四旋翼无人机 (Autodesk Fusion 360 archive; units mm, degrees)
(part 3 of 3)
sketch "草图4" plane through (0, 1.5, 0) normal (0, 1, 0) x axis (-1, 0, 0)
  line L1 (-17, -12) -> (-2, -12)
  line L2 (-18, -13) -> (-17, -12)
  line L3 (-18, -15) -> (-18, -13)
  line L4 (15, -18) -> (-15, -18)
  line L5 (18, -13) -> (18, -15)
  line L6 (17, -12) -> (18, -13)
  line L7 (17, 12) -> (17, -12)
  line L8 (18, 13) -> (17, 12)
  line L9 (18, 15) -> (18, 13)
  line L10 (-15, 18) -> (15, 18)
  line L11 (-18, 13) -> (-18, 15)
  line L12 (-17, 12) -> (-18, 13)
  line L13 (-17, -8.9856) -> (-17, 12)
  line L14 (-16.0181, -7.3474) -> (-17, -8.9856)
  line L15 (-16.0181, 3) -> (-16.0181, -7.3474)
  line L16 (-2, 3) -> (-16.0181, 3)
  line L17 (-2, -12) -> (-2, 3)
  line L18 (-5, 13.5) -> (5, 13.5)
  line L19 (-5, 18) -> (-5, 13.5)
  line L20 (5, 18) -> (-5, 18)
  line L21 (5, 13.5) -> (5, 18)
  arc A1 centre (-15, -15) radius 3 clockwise from (-15, -18) to (-18, -15)
  arc A2 centre (15, -15) radius 3 clockwise from (18, -15) to (15, -18)
  arc A3 centre (15, 15) radius 3 clockwise from (15, 18) to (18, 15)
  arc A4 centre (-15, 15) radius 3 clockwise from (-18, 15) to (-15, 18)
  circle C1 centre (-15, 15) radius 2
  circle C2 centre (15, 15) radius 2
  circle C3 centre (15, -15) radius 2
  circle C4 centre (-15, -15) radius 2
  point P33 (-5, 18)
  point P35 (0, 13.5)
  point P1 (0, 0)
  point P31 (5, 13.5)
  point P32 (-5, 13.5)
  horizontal L18
  vertical L19
  horizontal L20
  vertical L21
  coincident L10 P33
  midpoint L18 P35
  vertical P1 P35
  dimension "d23" distance P31 P32 = 10
  dimension "d24" distance P32 P33 = 4.5
extrude "拉伸4" add sketch "草图4" profile of L10 L18 L19 L20 L21 along normal blind 3
sketch "草图5" plane through (0, 1.5, 0) normal (0, 1, 0) x axis (-1, 0, 0)
  line L1 (-5, 18) -> (-5, 13.5)
  line L2 (-15, 18) -> (-5, 18)
  line L3 (-18, 13) -> (-18, 15)
  line L4 (-17, 12) -> (-18, 13)
  line L5 (-17, -8.9856) -> (-17, 12)
  line L6 (-16.0181, -7.3474) -> (-17, -8.9856)
  line L7 (-16.0181, 3) -> (-16.0181, -7.3474)
  line L8 (-2, 3) -> (-16.0181, 3)
  line L9 (-2, -12) -> (-2, 3)
  line L10 (-17, -12) -> (-2, -12)
  line L11 (-18, -13) -> (-17, -12)
  line L12 (-18, -15) -> (-18, -13)
  line L13 (15, -18) -> (-15, -18)
  line L14 (18, -13) -> (18, -15)
  line L15 (17, -12) -> (18, -13)
  line L16 (17, 12) -> (17, -12)
  line L17 (18, 13) -> (17, 12)
  line L18 (18, 15) -> (18, 13)
  line L19 (5, 18) -> (15, 18)
  line L20 (5, 13.5) -> (5, 18)
  line L21 (-5, 13.5) -> (5, 13.5)
  line L22 (6.5346, -12) -> (11, -12)
  line L23 (6.5346, -2.267) -> (6.5346, -12)
  line L24 (11, -2.267) -> (6.5346, -2.267)
  line L25 (11, -12) -> (11, -2.267)
  line L26 (6.2413, 4.9227) -> (11.8936, 4.9227)
  line L27 (6.2413, 10.575) -> (6.2413, 4.9227)
  line L28 (11.8936, 10.575) -> (6.2413, 10.575)
  line L29 (11.8936, 4.9227) -> (11.8936, 10.575)
  line L30 (4.0838, 6.9737) -> (5.1098, 6.9737)
  line L31 (4.0838, 8.524) -> (4.0838, 6.9737)
  line L32 (5.1098, 8.524) -> (4.0838, 8.524)
  line L33 (5.1098, 6.9737) -> (5.1098, 8.524)
  line L34 (0.5, 6.4497) -> (3.0982, 6.4497)
  line L35 (0.5, 9.048) -> (0.5, 6.4497)
  line L36 (3.0982, 9.048) -> (0.5, 9.048)
  line L37 (3.0982, 6.4497) -> (3.0982, 9.048)
  line L38 (-6.7587, 4.9227) -> (-1.1064, 4.9227)
  line L39 (-9.9018, 6.4497) -> (-9.9018, 9.048)
  line L40 (-8.9162, 6.9737) -> (-7.8902, 6.9737)
  line L41 (-1.1064, 4.9227) -> (-1.1064, 10.575)
  line L42 (-12.5, 6.4497) -> (-9.9018, 6.4497)
  line L43 (-6.7587, 10.575) -> (-6.7587, 4.9227)
  line L44 (-12.5, 9.048) -> (-12.5, 6.4497)
  line L45 (-7.8902, 8.524) -> (-8.9162, 8.524)
  line L46 (-9.9018, 9.048) -> (-12.5, 9.048)
  line L47 (-8.9162, 8.524) -> (-8.9162, 6.9737)
  line L48 (-1.1064, 10.575) -> (-6.7587, 10.575)
  line L49 (-7.8902, 6.9737) -> (-7.8902, 8.524)
  arc A1 centre (-15, 15) radius 3 clockwise from (-18, 15) to (-15, 18)
  arc A2 centre (-15, -15) radius 3 clockwise from (-15, -18) to (-18, -15)
  arc A3 centre (15, -15) radius 3 clockwise from (18, -15) to (15, -18)
  arc A4 centre (15, 15) radius 3 clockwise from (15, 18) to (18, 15)
  circle C1 centre (15, -15) radius 2
  circle C2 centre (15, 15) radius 2
  circle C3 centre (-15, 15) radius 2
  circle C4 centre (-15, -15) radius 2
  point P51 (3.0982, 7.7488)
  point P52 (4.0838, 7.7488)
  point P53 (6.2413, 7.7488)
  horizontal L22
  vertical L23
  horizontal L24
  vertical L25
  horizontal L26
  vertical L27
  horizontal L28
  vertical L29
  horizontal L30
  vertical L31
  horizontal L32
  vertical L33
  horizontal L34
  vertical L35
  horizontal L36
  vertical L37
  equal L26 L27
  equal L34 L37
  midpoint L37 P51
  midpoint L31 P52
  horizontal P51 P52
  midpoint L27 P53
  horizontal P52 P53
  dimension "d29" R-Pattern1-uDistance = -13
  dimension "d30" R-Pattern1-vDistance = 0
extrude "拉伸5" add sketch "草图5" profile of L22 L23 L24 L25 L26 L27 L28 L29 L30 L31 L32 L33 L34 L35 L36 L37 L38 L39 L40 L41 L42 L43 L44 L45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 along normal blind 1
sketch "草图6" plane through (0, 1.5, 0) normal (0, 1, 0) x axis (-1, 0, 0)
  line L1 (11, -12) -> (11, -2.267)
  line L2 (6.5346, -12) -> (11, -12)
  line L3 (6.5346, -2.267) -> (6.5346, -12)
  line L4 (11, -2.267) -> (6.5346, -2.267)
  line L5 (3.0982, 6.4497) -> (3.0982, 9.048)
  line L6 (0.5, 6.4497) -> (3.0982, 6.4497)
  line L7 (0.5, 9.048) -> (0.5, 6.4497)
  line L8 (3.0982, 9.048) -> (0.5, 9.048)
  line L9 (5.1098, 6.9737) -> (5.1098, 8.524)
  line L10 (4.0838, 6.9737) -> (5.1098, 6.9737)
  line L11 (4.0838, 8.524) -> (4.0838, 6.9737)
  line L12 (5.1098, 8.524) -> (4.0838, 8.524)
  line L13 (-9.9018, 9.048) -> (-12.5, 9.048)
  line L14 (-9.9018, 6.4497) -> (-9.9018, 9.048)
  line L15 (-12.5, 6.4497) -> (-9.9018, 6.4497)
  line L16 (-12.5, 9.048) -> (-12.5, 6.4497)
  line L17 (-1.1064, 10.575) -> (-6.7587, 10.575)
  line L18 (-1.1064, 4.9227) -> (-1.1064, 10.575)
  line L19 (-6.7587, 4.9227) -> (-1.1064, 4.9227)
  line L20 (-6.7587, 10.575) -> (-6.7587, 4.9227)
  line L21 (11.8936, 4.9227) -> (11.8936, 10.575)
  line L22 (6.2413, 4.9227) -> (11.8936, 4.9227)
  line L23 (6.2413, 10.575) -> (6.2413, 4.9227)
  line L24 (11.8936, 10.575) -> (6.2413, 10.575)
  line L25 (-7.8902, 6.9737) -> (-7.8902, 8.524)
  line L26 (-8.9162, 6.9737) -> (-7.8902, 6.9737)
  line L27 (-8.9162, 8.524) -> (-8.9162, 6.9737)
  line L28 (-7.8902, 8.524) -> (-8.9162, 8.524)
  line L29 (-5, 18) -> (-5, 13.5)
  line L30 (-15, 18) -> (-5, 18)
  line L31 (-18, 13) -> (-18, 15)
  line L32 (-17, 12) -> (-18, 13)
  line L33 (-17, -8.9856) -> (-17, 12)
  line L34 (-16.0181, -7.3474) -> (-17, -8.9856)
  line L35 (-16.0181, 3) -> (-16.0181, -7.3474)
  line L36 (-2, 3) -> (-16.0181, 3)
  line L37 (-2, -12) -> (-2, 3)
  line L38 (-17, -12) -> (-2, -12)
  line L39 (-18, -13) -> (-17, -12)
  line L40 (-18, -15) -> (-18, -13)
  line L41 (15, -18) -> (-15, -18)
  line L42 (18, -13) -> (18, -15)
  line L43 (17, -12) -> (18, -13)
  line L44 (17, 12) -> (17, -12)
  line L45 (18, 13) -> (17, 12)
  line L46 (18, 15) -> (18, 13)
  line L47 (5, 18) -> (15, 18)
  line L48 (5, 13.5) -> (5, 18)
  line L49 (-5, 13.5) -> (5, 13.5)
  line L50 (9.3337, -1) -> (12, -1)
  line L51 (9.3337, 0.4013) -> (9.3337, -1)
  line L52 (12, 0.4013) -> (9.3337, 0.4013)
  line L53 (12, -1) -> (12, 0.4013)
  line L54 (9.3337, 1.5747) -> (12, 1.5747)
  line L55 (9.3337, 2.8319) -> (9.3337, 1.5747)
  line L56 (12, 2.8319) -> (9.3337, 2.8319)
  line L57 (12, 1.5747) -> (12, 2.8319)
  line L58 (5.8554, -0.7302) -> (7.4478, -0.7302)
  line L59 (5.8554, 2.2033) -> (5.8554, -0.7302)
  line L60 (7.4478, 2.2033) -> (5.8554, 2.2033)
  line L61 (7.4478, -0.7302) -> (7.4478, 2.2033)
  line L62 (1.6646, -11.4165) -> (3.0476, -11.4165)
  line L63 (1.6646, -10.6622) -> (1.6646, -11.4165)
  line L64 (3.0476, -10.6622) -> (1.6646, -10.6622)
  line L65 (3.0476, -11.4165) -> (3.0476, -10.6622)
  line L66 (1, -9.2374) -> (3.5505, -9.2374)
  line L67 (1, -8) -> (1, -9.2374)
  line L68 (3.5505, -8) -> (1, -8)
  line L69 (3.5505, -9.2374) -> (3.5505, -8)
  line L70 (1.6646, -7) -> (3, -7)
  line L71 (1.6646, -6.0524) -> (1.6646, -7)
  line L72 (3, -6.0524) -> (1.6646, -6.0524)
  line L73 (3, -7) -> (3, -6.0524)
  line L74 (1.6646, -1.4426) -> (3.9695, -1.4426)
  line L75 (1.6646, -0.3949) -> (1.6646, -1.4426)
  line L76 (3.9695, -0.3949) -> (1.6646, -0.3949)
  line L77 (3.9695, -1.4426) -> (3.9695, -0.3949)
  arc A1 centre (-15, 15) radius 3 clockwise from (-18, 15) to (-15, 18)
  arc A2 centre (-15, -15) radius 3 clockwise from (-15, -18) to (-18, -15)
  arc A3 centre (15, -15) radius 3 clockwise from (18, -15) to (15, -18)
  arc A4 centre (15, 15) radius 3 clockwise from (15, 18) to (18, 15)
  circle C1 centre (15, -15) radius 2
  circle C2 centre (15, 15) radius 2
  circle C3 centre (-15, 15) radius 2
  circle C4 centre (-15, -15) radius 2
  horizontal L50
  vertical L51
  horizontal L52
  vertical L53
  horizontal L54
  vertical L55
  horizontal L56
  vertical L57
  horizontal L58
  vertical L59
  horizontal L60
  vertical L61
  horizontal L62
  vertical L63
  horizontal L64
  vertical L65
  horizontal L66
  vertical L67
  horizontal L68
  vertical L69
  horizontal L70
  vertical L71
  horizontal L72
  vertical L73
  horizontal L74
  vertical L75
  horizontal L76
  vertical L77
extrude "拉伸6" add sketch "草图6" profile of L50 L51 L52 L53 L54 L55 L56 L57 L58 L59 L60 L61 L62 L63 L64 L65 L66 L67 L68 L69 L70 L71 L72 L73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 along normal blind 0.5
sketch "草图7" plane through (0, 0, 0) normal (0, -1, 0) x axis (1, 0, 0)
  line L1 (-17, 12) -> (-18, 13)
  line L2 (-17, -12) -> (-17, 12)
  line L3 (-18, -13) -> (-17, -12)
  line L4 (-18, -15) -> (-18, -13)
  line L5 (15, -18) -> (-15, -18)
  line L6 (18, -13) -> (18, -15)
  line L7 (17, -12) -> (18, -13)
  line L8 (17, 12) -> (17, -12)
  line L9 (18, 13) -> (17, 12)
  line L10 (18, 15) -> (18, 13)
  line L11 (-15, 18) -> (15, 18)
  line L12 (-18, 13) -> (-18, 15)
  line L13 (-4.5, -6) -> (5, -6)
  line L14 (-4.5, 3.5) -> (-4.5, -6)
  line L15 (5, 3.5) -> (-4.5, 3.5)
  line L16 (5, -6) -> (5, 3.5)
  circle C1 centre (-15, -15) radius 2
  circle C2 centre (-15, 15) radius 2
  circle C3 centre (15, 15) radius 2
  circle C4 centre (15, -15) radius 2
  arc A1 centre (-15, -15) radius 3 clockwise from (-15, -18) to (-18, -15)
  arc A2 centre (15, -15) radius 3 clockwise from (18, -15) to (15, -18)
  arc A3 centre (15, 15) radius 3 clockwise from (15, 18) to (18, 15)
  arc A4 centre (-15, 15) radius 3 clockwise from (-18, 15) to (-15, 18)
  point P27 (-4.5, -6)
  point P28 (-4.5, 3.5)
  horizontal L13
  vertical L14
  horizontal L15
  vertical L16
  equal L13 L16
  dimension "d35" distance P27 P28 = 9.5
  dimension "d36" distance L8 L16 = 12
  dimension "d40" distance L5 L13 = 12
circular_pattern "C-阵列" TotalAngle -90
chamfer "倒角2" distance 1
extrude "拉伸7" add sketch "草图7" profile of L13 L14 L15 L16 along normal blind 1
sketch "草图8" plane through (0, 0, 0) normal (0, -1, 0) x axis (1, 0, 0)
  line L1 (5, -6) -> (5, 3.5)
  line L2 (-4.5, -6) -> (5, -6)
  line L3 (-4.5, 3.5) -> (-4.5, -6)
  line L4 (5, 3.5) -> (-4.5, 3.5)
  line L5 (13, -18) -> (12, -17)
  line L6 (15, -18) -> (13, -18)
  line L7 (18, -13) -> (18, -15)
  line L8 (17, -12) -> (18, -13)
  line L9 (17, 12) -> (17, -12)
  line L10 (18, 13) -> (17, 12)
  line L11 (18, 15) -> (18, 13)
  line L12 (-15, 18) -> (15, 18)
  line L13 (-18, 13) -> (-18, 15)
  line L14 (-17, 12) -> (-18, 13)
  line L15 (-17, -12) -> (-17, 12)
  line L16 (-18, -13) -> (-17, -12)
  line L17 (-18, -15) -> (-18, -13)
  line L18 (-13, -18) -> (-15, -18)
  line L19 (-12, -17) -> (-13, -18)
  line L20 (12, -17) -> (-12, -17)
  line L21 (-12, -3.5) -> (-18, -3.5)
  line L22 (-12, -11) -> (-12, -3.5)
  line L23 (-18, -11) -> (-12, -11)
  line L24 (-18, -3.5) -> (-18, -11)
  arc A1 centre (15, -15) radius 3 clockwise from (18, -15) to (15, -18)
  arc A2 centre (15, 15) radius 3 clockwise from (15, 18) to (18, 15)
  arc A3 centre (-15, 15) radius 3 clockwise from (-18, 15) to (-15, 18)
  arc A4 centre (-15, -15) radius 3 clockwise from (-15, -18) to (-18, -15)
  circle C1 centre (15, -15) radius 2
  circle C2 centre (15, 15) radius 2
  circle C3 centre (-15, 15) radius 2
  circle C4 centre (-15, -15) radius 2
  point P24 (-18, -13)
  point P37 (-18, -11)
  point P34 (-18, -3.5)
  point P35 (-12, -3.5)
  horizontal L21
  vertical L22
  horizontal L23
  vertical L24
  vertical P24 P37
  dimension "d43" distance P34 P37 = 7.5
  dimension "d44" distance P34 P35 = 6
  dimension "d45" distance L18 L23 = 7
extrude "拉伸8" add sketch "草图8" profile of L15 L21 L22 L23 L24 along normal blind 3
sketch "草图9" plane through (0, 0, 0) normal (0, -1, 0) x axis (1, 0, 0)
  line L1 (-17, -11) -> (-12, -11)
  line L2 (-17, -12) -> (-17, -11)
  line L3 (-18, -13) -> (-17, -12)
  line L4 (-18, -15) -> (-18, -13)
  line L5 (-13, -18) -> (-15, -18)
  line L6 (-12, -17) -> (-13, -18)
  line L7 (12, -17) -> (-12, -17)
  line L8 (13, -18) -> (12, -17)
  line L9 (15, -18) -> (13, -18)
  line L10 (18, -13) -> (18, -15)
  line L11 (17, -12) -> (18, -13)
  line L12 (17, 12) -> (17, -12)
  line L13 (18, 13) -> (17, 12)
  line L14 (18, 15) -> (18, 13)
  line L15 (-15, 18) -> (15, 18)
  line L16 (-18, 13) -> (-18, 15)
  line L17 (-17, 12) -> (-18, 13)
  line L18 (-17, -3.5) -> (-17, 12)
  line L19 (-12, -3.5) -> (-17, -3.5)
  line L20 (-12, -11) -> (-12, -3.5)
  line L21 (5, -6) -> (5, 3.5)
  line L22 (-4.5, -6) -> (5, -6)
  line L23 (-4.5, 3.5) -> (-4.5, -6)
  line L24 (5, 3.5) -> (-4.5, 3.5)
  line L25 (-14.4436, 2.0212) -> (-16.5885, 2.0212)
  line L26 (-14.4436, -1.9949) -> (-14.4436, 2.0212)
  line L27 (-16.5885, -1.9949) -> (-14.4436, -1.9949)
  line L28 (-16.5885, 2.0212) -> (-16.5885, -1.9949)
  arc A1 centre (-15, -15) radius 3 clockwise from (-15, -18) to (-18, -15)
  arc A2 centre (15, -15) radius 3 clockwise from (18, -15) to (15, -18)
  arc A3 centre (15, 15) radius 3 clockwise from (15, 18) to (18, 15)
  arc A4 centre (-15, 15) radius 3 clockwise from (-18, 15) to (-15, 18)
  circle C1 centre (15, -15) radius 2
  circle C2 centre (15, 15) radius 2
  circle C3 centre (-15, 15) radius 2
  circle C4 centre (-15, -15) radius 2
  horizontal L25
  vertical L26
  horizontal L27
  vertical L28
extrude "拉伸9" add sketch "草图9" profile of L25 L26 L27 L28 along normal blind 1

design "舵机控制电板"
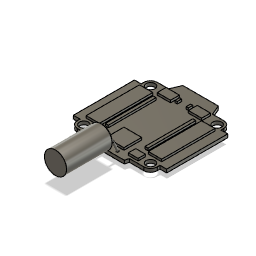
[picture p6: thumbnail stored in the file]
sketch "草图1" plane through (0, 0, 0) normal (0, 1, 0) x axis (1, 0, 0)
  line L1 (-18, 18) -> (18, 18)
  line L2 (-18, -18) -> (-18, 18)
  line L3 (18, -18) -> (-18, -18)
  line L4 (18, 18) -> (18, -18)
  line L5 (-18, -18) -> (18, 18)
  line L6 (18, -18) -> (-18, 18)
  line L7 (17, 13) -> (14, 13)
  circle C1 centre (15, 15) radius 2
  circle C2 centre (-15, 15) radius 2
  circle C3 centre (-15, -15) radius 2
  circle C4 centre (15, -15) radius 2
  point P6 (0, 0)
  point P1 (0, 0)
  point P7 (15, 15)
  point P4 (-18, -18)
  point P5 (18, -18)
  point P3 (-18, 18)
  horizontal L1
  perpendicular L1 L2
  parallel L1 L3
  parallel L2 L4
  coincident L5 P6
  coincident L6 P6
  coincident P1 P6
  coincident L5 P7
  horizontal L7
  tangent C1 L7
  dimension "d1" distance P4 P5 = 36
  dimension "d2" distance P3 P4 = 36
  dimension "d3" diameter C1 = 4
  dimension "d4" distance P6 L7 = 13 (= "( 26 / 2 ) * 1 mm")
  dimension "d6" C-Pattern1-Angle = 360
extrude "拉伸1" new body sketch "草图1" profile of L1 L2 L3 L4 C1 C2 C3 C4 along normal blind 1.5
fillet "圆角1" radius 3
sketch "草图10" plane through (0, 1.5, 0) normal (0, 1, 0) x axis (-1, 0, 0)
  line L1 (18, 15) -> (18, -15)
  line L2 (-15, 18) -> (15, 18)
  line L3 (-18, -15) -> (-18, 15)
  line L4 (15, -18) -> (-15, -18)
  line L5 (21, -13.75) -> (-21, -13.75)
  line L6 (21, 13.75) -> (21, -13.75)
  line L7 (-21, 13.75) -> (21, 13.75)
  line L8 (-21, -13.75) -> (-21, 13.75)
  line L9 (21, 13.75) -> (-21, -13.75)
  line L10 (-21, 13.75) -> (21, -13.75)
  circle C1 centre (-15, -15) radius 2
  circle C2 centre (-15, 15) radius 2
  circle C3 centre (15, 15) radius 2
  circle C4 centre (15, -15) radius 2
  arc A1 centre (15, -15) radius 3 clockwise from (18, -15) to (15, -18)
  arc A2 centre (15, 15) radius 3 clockwise from (15, 18) to (18, 15)
  arc A3 centre (-15, 15) radius 3 clockwise from (-18, 15) to (-15, 18)
  arc A4 centre (-15, -15) radius 3 clockwise from (-15, -18) to (-18, -15)
  point P22 (0, 0)
  point P1 (0, 0)
  point P19 (21, -13.75)
  point P20 (21, 13.75)
  horizontal L5
  perpendicular L5 L6
  parallel L5 L7
  parallel L6 L8
  coincident L9 P22
  coincident L10 P22
  coincident P1 P22
  dimension "d50" distance P19 P20 = 27.5
extrude "拉伸10" add sketch "草图10" profile of L1 L3 L5 L6 L7 L8 to an object
sketch "草图11" plane through (0, 0, 0) normal (0, 1, 0) x axis (1, 0, 0)
  line L1 (8, -19.8) -> (8.4609, -18)
  line L2 (-8, -19.8) -> (8, -19.8)
  line L3 (-8.4609, -18) -> (-8, -19.8)
  line L4 (8, 22.5) -> (9.8811, 18)
  line L5 (-8, 22.5) -> (8, 22.5)
  line L6 (-9.8811, 18) -> (-8, 22.5)
  line L7 (-15, 18) -> (15, 18)
  line L8 (15, -18) -> (-15, -18)
  point P10 (0, 22.5)
  point P1 (0, 0)
  point P11 (0, -19.8)
  point P6 (9.8811, 18)
  point P9 (-9.8811, 18)
  point P2 (8.4609, -18)
  point P5 (-8.4609, -18)
  point P7 (8, 22.5)
  point P8 (-8, 22.5)
  horizontal L2
  horizontal L5
  midpoint L5 P10
  vertical P1 P10
  midpoint L2 P11
  vertical P1 P11
  equal L1 L3
  equal L4 L6
  coincident P6 L7
  coincident P9 L7
  coincident P2 L8
  coincident P5 L8
  equal L2 L5
  dimension "d53" distance L5 L7 = 4.5
  dimension "d54" distance L2 L8 = 1.8
  dimension "d55" distance P7 P8 = 16
extrude "拉伸11" add sketch "草图11" to an object
sketch "草图12" plane through (0, 1.5, 0) normal (0, 1, 0) x axis (-1, 0, 0)
  line L1 (18, -13.75) -> (18, -15)
  line L2 (21, -13.75) -> (18, -13.75)
  line L3 (21, 13.75) -> (21, -13.75)
  line L4 (18, 13.75) -> (21, 13.75)
  line L5 (18, 15) -> (18, 13.75)
  line L6 (8.4609, 18) -> (15, 18)
  line L7 (8, 19.8) -> (8.4609, 18)
  line L8 (-8, 19.8) -> (8, 19.8)
  line L9 (-8.4609, 18) -> (-8, 19.8)
  line L10 (-15, 18) -> (-8.4609, 18)
  line L11 (-18, 13.75) -> (-18, 15)
  line L12 (-21, 13.75) -> (-18, 13.75)
  line L13 (-21, -13.75) -> (-21, 13.75)
  line L14 (-18, -13.75) -> (-21, -13.75)
  line L15 (-18, -15) -> (-18, -13.75)
  line L16 (-9.8811, -18) -> (-15, -18)
  line L17 (-8, -22.5) -> (-9.8811, -18)
  line L18 (8, -22.5) -> (-8, -22.5)
  line L19 (9.8811, -18) -> (8, -22.5)
  line L20 (15, -18) -> (9.8811, -18)
  line L21 (-11, -12) -> (-17, -12)
  line L22 (-11, 12) -> (-11, -12)
  line L23 (-17, 12) -> (-11, 12)
  line L24 (-17, -12) -> (-17, 12)
  line L25 (-8.2645, -10.7571) -> (-9.6051, -10.7571)
  line L26 (-8.2645, 10.7571) -> (-8.2645, -10.7571)
  line L27 (-9.6051, 10.7571) -> (-8.2645, 10.7571)
  line L28 (-9.6051, -10.7571) -> (-9.6051, 10.7571)
  line L29 (-4, -17) -> (-10, -17)
  line L30 (-4, -13) -> (-4, -17)
  line L31 (-10, -13) -> (-4, -13)
  line L32 (-10, -17) -> (-10, -13)
  line L33 (-3, -16) -> (-2, -16)
  line L34 (-3, -14) -> (-3, -16)
  line L35 (-2, -14) -> (-3, -14)
  line L36 (-2, -16) -> (-2, -14)
  line L37 (-7, 13.6909) -> (-11.3908, 13.6909)
  line L38 (-7, 17) -> (-7, 13.6909)
  line L39 (-11.3908, 17) -> (-7, 17)
  line L40 (-11.3908, 13.6909) -> (-11.3908, 17)
  circle C1 centre (-15, -15) radius 2
  circle C2 centre (-15, 15) radius 2
  circle C3 centre (15, 15) radius 2
  circle C4 centre (15, -15) radius 2
  arc A1 centre (15, -15) radius 3 clockwise from (18, -15) to (15, -18)
  arc A2 centre (15, 15) radius 3 clockwise from (15, 18) to (18, 15)
  arc A3 centre (-15, 15) radius 3 clockwise from (-18, 15) to (-15, 18)
  arc A4 centre (-15, -15) radius 3 clockwise from (-15, -18) to (-18, -15)
  point P42 (-9.6051, 0)
  point P43 (-11, 0)
  point P1 (0, 0)
  horizontal L21
  vertical L22
  horizontal L23
  vertical L24
  horizontal L25
  vertical L26
  horizontal L27
  vertical L28
  midpoint L28 P42
  midpoint L22 P43
  horizontal P42 P43
  horizontal P1 P42
  horizontal L29
  vertical L30
  horizontal L31
  vertical L32
  horizontal L33
  vertical L34
  horizontal L35
  vertical L36
  horizontal L37
  vertical L38
  horizontal L39
  vertical L40
extrude "拉伸12" add sketch "草图12" profile of L21 L22 L23 L24 L25 L26 L27 L28 L29 L30 L31 L32 L33 L34 L35 L36 L37 L38 L39 L40 along normal blind 1
mirror "镜像2" mirrorStitchTolerance 0.1
work_plane "工作平面1"
mirror "镜像3" mirrorStitchTolerance 0.1
sketch "草图13" plane through (0, 1.5, 0) normal (0, 1, 0) x axis (-1, 0, 0)
  line L1 (11.3908, 17) -> (7, 17)
  line L2 (11.3908, 13.6909) -> (11.3908, 17)
  line L3 (7, 13.6909) -> (11.3908, 13.6909)
  line L4 (7, 17) -> (7, 13.6909)
  line L5 (17, 12) -> (11, 12)
  line L6 (17, -12) -> (17, 12)
  line L7 (11, -12) -> (17, -12)
  line L8 (11, 12) -> (11, -12)
  line L9 (2, -14) -> (2, -16)
  line L10 (3, -14) -> (2, -14)
  line L11 (3, -16) -> (3, -14)
  line L12 (2, -16) -> (3, -16)
  line L13 (9.6051, 10.7571) -> (8.2645, 10.7571)
  line L14 (9.6051, -10.7571) -> (9.6051, 10.7571)
  line L15 (8.2645, -10.7571) -> (9.6051, -10.7571)
  line L16 (8.2645, 10.7571) -> (8.2645, -10.7571)
  line L17 (10, -13) -> (4, -13)
  line L18 (10, -17) -> (10, -13)
  line L19 (4, -17) -> (10, -17)
  line L20 (4, -13) -> (4, -17)
  line L21 (-7, 17) -> (-11.3908, 17)
  line L22 (-7, 13.6909) -> (-7, 17)
  line L23 (-11.3908, 13.6909) -> (-7, 13.6909)
  line L24 (-11.3908, 17) -> (-11.3908, 13.6909)
  line L25 (-11, 12) -> (-17, 12)
  line L26 (-11, -12) -> (-11, 12)
  line L27 (-17, -12) -> (-11, -12)
  line L28 (-17, 12) -> (-17, -12)
  line L29 (-2, -16) -> (-2, -14)
  line L30 (-3, -16) -> (-2, -16)
  line L31 (-3, -14) -> (-3, -16)
  line L32 (-2, -14) -> (-3, -14)
  line L33 (-8.2645, 10.7571) -> (-9.6051, 10.7571)
  line L34 (-8.2645, -10.7571) -> (-8.2645, 10.7571)
  line L35 (-9.6051, -10.7571) -> (-8.2645, -10.7571)
  line L36 (-9.6051, 10.7571) -> (-9.6051, -10.7571)
  line L37 (-4, -13) -> (-10, -13)
  line L38 (-4, -17) -> (-4, -13)
  line L39 (-10, -17) -> (-4, -17)
  line L40 (-10, -13) -> (-10, -17)
  line L41 (18, -13.75) -> (18, -15)
  line L42 (21, -13.75) -> (18, -13.75)
  line L43 (21, 13.75) -> (21, -13.75)
  line L44 (18, 13.75) -> (21, 13.75)
  line L45 (18, 15) -> (18, 13.75)
  line L46 (8.4609, 18) -> (15, 18)
  line L47 (8, 19.8) -> (8.4609, 18)
  line L48 (-8, 19.8) -> (8, 19.8)
  line L49 (-8.4609, 18) -> (-8, 19.8)
  line L50 (-15, 18) -> (-8.4609, 18)
  line L51 (-18, 13.75) -> (-18, 15)
  line L52 (-21, 13.75) -> (-18, 13.75)
  line L53 (-21, -13.75) -> (-21, 13.75)
  line L54 (-18, -13.75) -> (-21, -13.75)
  line L55 (-18, -15) -> (-18, -13.75)
  line L56 (-9.8811, -18) -> (-15, -18)
  line L57 (-8, -22.5) -> (-9.8811, -18)
  line L58 (8, -22.5) -> (-8, -22.5)
  line L59 (9.8811, -18) -> (8, -22.5)
  line L60 (15, -18) -> (9.8811, -18)
  line L61 (4, 16) -> (-4, 16)
  line L62 (4, 8) -> (4, 16)
  line L63 (-4, 8) -> (4, 8)
  line L64 (-4, 16) -> (-4, 8)
  line L65 (4, 8) -> (-4, 16)
  line L66 (-4, 8) -> (4, 16)
  circle C1 centre (-15, -15) radius 2
  circle C2 centre (-15, 15) radius 2
  circle C3 centre (15, 15) radius 2
  circle C4 centre (15, -15) radius 2
  arc A1 centre (15, -15) radius 3 clockwise from (18, -15) to (15, -18)
  arc A2 centre (15, 15) radius 3 clockwise from (15, 18) to (18, 15)
  arc A3 centre (-15, 15) radius 3 clockwise from (-18, 15) to (-15, 18)
  arc A4 centre (-15, -15) radius 3 clockwise from (-15, -18) to (-18, -15)
  point P78 (0, 12)
  horizontal L61
  perpendicular L61 L62
  parallel L61 L63
  parallel L62 L64
  coincident L65 P78
  coincident L66 P78
  equal L63 L64
extrude "拉伸13" add sketch "草图13" profile of L61 L62 L63 L64 along normal blind 1
sketch "草图14" plane through (0, 0, 0) normal (1, 0, 0) x axis (0, 0, -1)
  line L1 (-42.8, 13) -> (-21.8, 13)
  line L2 (-42.8, 8) -> (-42.8, 13)
  line L3 (-21.8, 8) -> (-42.8, 8)
  line L4 (-21.8, 13) -> (-21.8, 8)
  line L5 (-13.75, 0) -> (13.75, 0)
  line L6 (-19.8, 1.5) -> (-19.8, 0)
  point P3 (-42.8, 13)
  point P4 (-42.8, 8)
  point P2 (-21.8, 13)
  horizontal L1
  vertical L2
  horizontal L3
  vertical L4
  dimension "d66" distance P3 P4 = 5
  dimension "d67" distance P2 P3 = 21
  dimension "d68" distance L1 L5 = 13
  dimension "d69" distance L4 L6 = 2
revolve "旋转" sketch "草图14" AlongAngle 360
fillet "圆角2" radius 0.5
work_plane "工作平面2" AlongDistance 3
sketch "草图15" plane through (3, 0, 0) normal (1, 0, 0) x axis (0, 0, -1)
  line L1 (-20.9439, 7) -> (-21.8, 7)
  line L2 (-17.8, 1.5) -> (-20.0335, 6.4138)
  line L3 (-21.8, 3.5) -> (-21.8, 12.5)
  arc A1 centre (-20.9439, 6) radius 1 clockwise from (-20.9439, 7) to (-20.0335, 6.4138)
  point P2 (-21.8, 7)
  horizontal L1
  tangent L1 A1
  tangent L2 A1
  coincident P2 L3
  dimension "d74" radius A1 = 1
sketch "草图16" plane through (0, 0, 21.8) normal (0, 0, -1) x axis (-1, 0, 0)
  circle C1 centre (0, 8) radius 4.5
  circle C2 centre (-3, 7) radius 0.5
  point P3 (-3, 7)
  point P4 (-3, 7)
  coincident P3 P4
  dimension "d75" diameter C2 = 1
sweep "扫掠" sketch "草图16" TwistAngle 0 TaperAngle 0
mirror "镜像4" mirrorStitchTolerance 0.1
sketch "草图17" plane through (0, 0, 0) normal (0, -1, 0) x axis (1, 0, 0)
  line L1 (-7, 17) -> (-11.3908, 17)
  line L2 (-7, 13.6909) -> (-7, 17)
  line L3 (-11.3908, 13.6909) -> (-7, 13.6909)
  line L4 (-11.3908, 17) -> (-11.3908, 13.6909)
  line L5 (-11, 12) -> (-17, 12)
  line L6 (-11, -12) -> (-11, 12)
  line L7 (-17, -12) -> (-11, -12)
  line L8 (-17, 12) -> (-17, -12)
  line L9 (-2, -16) -> (-2, -14)
  line L10 (-3, -16) -> (-2, -16)
  line L11 (-3, -14) -> (-3, -16)
  line L12 (-2, -14) -> (-3, -14)
  line L13 (-8.2645, 10.7571) -> (-9.6051, 10.7571)
  line L14 (-8.2645, -10.7571) -> (-8.2645, 10.7571)
  line L15 (-9.6051, -10.7571) -> (-8.2645, -10.7571)
  line L16 (-9.6051, 10.7571) -> (-9.6051, -10.7571)
  line L17 (-4, -13) -> (-10, -13)
  line L18 (-4, -17) -> (-4, -13)
  line L19 (-10, -17) -> (-4, -17)
  line L20 (-10, -13) -> (-10, -17)
  line L21 (11.3908, 17) -> (7, 17)
  line L22 (11.3908, 13.6909) -> (11.3908, 17)
  line L23 (7, 13.6909) -> (11.3908, 13.6909)
  line L24 (7, 17) -> (7, 13.6909)
  line L25 (17, 12) -> (11, 12)
  line L26 (17, -12) -> (17, 12)
  line L27 (11, -12) -> (17, -12)
  line L28 (11, 12) -> (11, -12)
  line L29 (2, -14) -> (2, -16)
  line L30 (3, -14) -> (2, -14)
  line L31 (3, -16) -> (3, -14)
  line L32 (2, -16) -> (3, -16)
  line L33 (9.6051, 10.7571) -> (8.2645, 10.7571)
  line L34 (9.6051, -10.7571) -> (9.6051, 10.7571)
  line L35 (8.2645, -10.7571) -> (9.6051, -10.7571)
  line L36 (8.2645, 10.7571) -> (8.2645, -10.7571)
  line L37 (10, -13) -> (4, -13)
  line L38 (10, -17) -> (10, -13)
  line L39 (4, -17) -> (10, -17)
  line L40 (4, -13) -> (4, -17)
  line L41 (-9.8811, -18) -> (-15, -18)
  line L42 (-8, -22.5) -> (-9.8811, -18)
  line L43 (8, -22.5) -> (-8, -22.5)
  line L44 (9.8811, -18) -> (8, -22.5)
  line L45 (15, -18) -> (9.8811, -18)
  line L46 (18, -13.75) -> (18, -15)
  line L47 (21, -13.75) -> (18, -13.75)
  line L48 (21, 13.75) -> (21, -13.75)
  line L49 (18, 13.75) -> (21, 13.75)
  line L50 (18, 15) -> (18, 13.75)
  line L51 (8.4609, 18) -> (15, 18)
  line L52 (8, 19.8) -> (8.4609, 18)
  line L53 (-8, 19.8) -> (8, 19.8)
  line L54 (-8.4609, 18) -> (-8, 19.8)
  line L55 (-15, 18) -> (-8.4609, 18)
  line L56 (-18, 13.75) -> (-18, 15)
  line L57 (-21, 13.75) -> (-18, 13.75)
  line L58 (-21, -13.75) -> (-21, 13.75)
  line L59 (-18, -13.75) -> (-21, -13.75)
  line L60 (-18, -15) -> (-18, -13.75)
  line L61 (-4.75, -22.5) -> (4.75, -22.5)
  line L62 (-4.75, -18) -> (-4.75, -22.5)
  line L63 (4.75, -18) -> (-4.75, -18)
  line L64 (4.75, -22.5) -> (4.75, -18)
  line L65 (-4.75, -18) -> (4.75, -22.5)
  line L66 (4.75, -18) -> (-4.75, -22.5)
  arc A1 centre (-15, -15) radius 3 clockwise from (-15, -18) to (-18, -15)
  arc A2 centre (15, -15) radius 3 clockwise from (18, -15) to (15, -18)
  arc A3 centre (15, 15) radius 3 clockwise from (15, 18) to (18, 15)
  arc A4 centre (-15, 15) radius 3 clockwise from (-18, 15) to (-15, 18)
  circle C1 centre (15, -15) radius 2
  circle C2 centre (15, 15) radius 2
  circle C3 centre (-15, 15) radius 2
  circle C4 centre (-15, -15) radius 2
  point P78 (0, -20.25)
  point P75 (-4.75, -22.5)
  point P1 (0, 0)
  point P74 (4.75, -22.5)
  point P77 (4.75, -18)
  horizontal L61
  perpendicular L61 L62
  parallel L61 L63
  parallel L62 L64
  coincident L65 P78
  coincident L66 P78
  coincident L43 P75
  vertical P1 P78
  dimension "d84" distance P74 P75 = 9.5
  dimension "d85" distance P74 P77 = 4.5
extrude "拉伸14" add sketch "草图17" profile of L43 L61 L62 L63 L64 along normal blind 2.5
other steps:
step "拉伸" AlongDistance 1 TaperAngle 0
